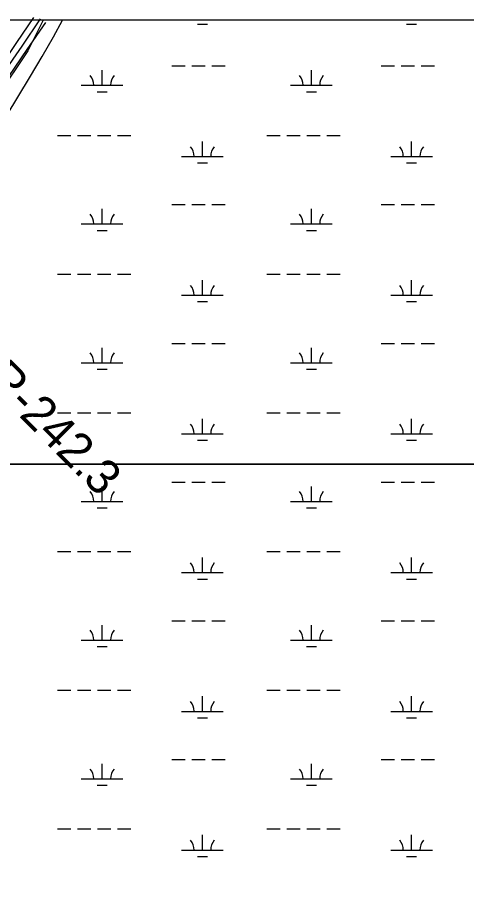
# Model space of a CAD drawing. Extents: x 3281947 to 3319794, y 715894 to 741249.
# Drawn here: x 3309600 to 3310677, y 737375 to 739476 of the extents above; entities that cross this region are included whole.
import ezdxf

# ---------------------------------------------------------------- set-up
doc = ezdxf.new("R2010")
doc.units = 0
for name, color, linetype in [('V-GRID-FRAM', 7, 'Continuous'), ('V-RIVR-RANG-IDEN', 7, 'Continuous'), ('V-ROAD-CNTR', 7, 'Continuous'), ('V-SITE-VEGE', 7, 'Continuous'), ('V-TOPO-MINR', 7, 'Continuous'), ('V-WETL-SWMP', 7, 'Continuous')]:
    doc.layers.add(name, color=color, linetype=linetype)

msp = doc.modelspace()

# ---------------------------------------------------------------- linework, layer by layer
at = {"layer": 'V-GRID-FRAM'}
msp.add_lwpolyline([(3286080.7, 739456.2), (3317564.6, 739474.5), (3317583.1, 721289.3), (3286083.3, 721271), (3286080.7, 739456.2)], dxfattribs=at)
at = {"layer": 'V-ROAD-CNTR'}
for points in [[(3309638.7, 739475.9), (3309597.9, 739416.1), (3309553.5, 739350.9), (3309551.3, 739347.7), (3309549.1, 739344.5), (3309547.1, 739341.4), (3309545.1, 739338.3), (3309541.4, 739332.5), (3309538, 739326.9), (3309534.8, 739321.7), (3309531.9, 739316.8), (3309529.2, 739312.2), (3309526.7, 739307.9), (3309524.3, 739303.8), (3309520, 739296.1), (3309516.3, 739289.4), (3309513.1, 739283.5), (3309507.6, 739273.2), (3309503.4, 739265.5), (3309491.2, 739242.3)], [(3309654.7, 739472.7), (3309610.3, 739407.6), (3309565.9, 739342.5), (3309563.7, 739339.3), (3309561.7, 739336.2), (3309559.7, 739333.2), (3309557.8, 739330.2), (3309554.1, 739324.5), (3309550.8, 739319.1), (3309547.7, 739314), (3309544.8, 739309.2), (3309542.1, 739304.7), (3309539.7, 739300.4), (3309537.4, 739296.4), (3309533.1, 739288.8), (3309529.5, 739282.2), (3309526.3, 739276.4), (3309520.8, 739266.2), (3309516.7, 739258.5), (3309504.5, 739235.3)], [(3309667.1, 739464.3), (3309622.7, 739399.2), (3309578.3, 739334.1), (3309576.2, 739331), (3309574.2, 739327.9), (3309572.2, 739325), (3309570.4, 739322.1), (3309566.8, 739316.5), (3309563.5, 739311.2), (3309560.5, 739306.3), (3309557.7, 739301.5), (3309555.1, 739297.1), (3309552.7, 739292.9), (3309550.4, 739289), (3309546.2, 739281.5), (3309542.6, 739275), (3309539.5, 739269.2), (3309534, 739259.1), (3309529.9, 739251.4), (3309517.8, 739228.4)]]:
    msp.add_lwpolyline(points, dxfattribs=at)
at = {"layer": 'V-SITE-VEGE'}
msp.add_line((3313381, 739472.1), (3309489.2, 739469.8), dxfattribs=at)
at = {"layer": 'V-TOPO-MINR'}
msp.add_lwpolyline([(3309520.4, 739144.1), (3309522, 739147.2), (3309534.3, 739170.3), (3309546.8, 739193.3), (3309559.8, 739216.1), (3309573.1, 739238.6), (3309631.4, 739335.3), (3309659.1, 739382.4), (3309686.2, 739429.8), (3309708, 739469.9)], dxfattribs=at)
at = {"layer": 'V-WETL-SWMP'}
for p, q in [((3309661.3, 739469.9), (3309624.5, 739396.3)), ((3313381, 739472.1), (3309661.3, 739469.9)), ((3310031.5, 739459.8), (3310055.5, 739459.8)), ((3310533.4, 739459.8), (3310557.4, 739459.8)), ((3309624.5, 739396.3), (3309546.4, 739279.2)), ((3309803, 739313.4), (3309803, 739349.4)), ((3309970.1, 739359.8), (3310002.1, 739359.8)), ((3310018.1, 739359.8), (3310050.1, 739359.8)), ((3310066.1, 739359.8), (3310098.1, 739359.8)), ((3310304.9, 739313.4), (3310304.9, 739349.4)), ((3310472, 739359.8), (3310504, 739359.8)), ((3310520, 739359.8), (3310552, 739359.8)), ((3310568, 739359.8), (3310600, 739359.8)), ((3309753, 739313.4), (3309853, 739313.4)), ((3310254.9, 739313.4), (3310354.9, 739313.4)), ((3309791, 739297.9), (3309815, 739297.9)), ((3310292.9, 739297.9), (3310316.9, 739297.9)), ((3309696.2, 739193.3), (3309728.2, 739193.3)), ((3309744.2, 739193.3), (3309776.2, 739193.3)), ((3309792.2, 739193.3), (3309824.2, 739193.3)), ((3309840.2, 739193.3), (3309872.2, 739193.3)), ((3310198.1, 739193.3), (3310230.1, 739193.3)), ((3310246.1, 739193.3), (3310278.1, 739193.3)), ((3310294.1, 739193.3), (3310326.1, 739193.3)), ((3310342.1, 739193.3), (3310374.1, 739193.3)), ((3310043.5, 739142.5), (3310043.5, 739178.5)), ((3310545.4, 739142.5), (3310545.4, 739178.5)), ((3309993.5, 739142.5), (3310093.5, 739142.5)), ((3310495.4, 739142.5), (3310595.4, 739142.5)), ((3310031.5, 739127.1), (3310055.5, 739127.1)), ((3310533.4, 739127.1), (3310557.4, 739127.1)), ((3309970.1, 739027.1), (3310002.1, 739027.1)), ((3310018.1, 739027.1), (3310050.1, 739027.1)), ((3310066.1, 739027.1), (3310098.1, 739027.1)), ((3310472, 739027.1), (3310504, 739027.1)), ((3310520, 739027.1), (3310552, 739027.1)), ((3310568, 739027.1), (3310600, 739027.1)), ((3309803, 738980.7), (3309803, 739016.7)), ((3310304.9, 738980.7), (3310304.9, 739016.7)), ((3309753, 738980.7), (3309853, 738980.7)), ((3309791, 738965.3), (3309815, 738965.3)), ((3310254.9, 738980.7), (3310354.9, 738980.7)), ((3310292.9, 738965.3), (3310316.9, 738965.3)), ((3309696.2, 738860.6), (3309728.2, 738860.6)), ((3309744.2, 738860.6), (3309776.2, 738860.6)), ((3309792.2, 738860.6), (3309824.2, 738860.6)), ((3309840.2, 738860.6), (3309872.2, 738860.6)), ((3310198.1, 738860.6), (3310230.1, 738860.6)), ((3310246.1, 738860.6), (3310278.1, 738860.6)), ((3310294.1, 738860.6), (3310326.1, 738860.6)), ((3310342.1, 738860.6), (3310374.1, 738860.6)), ((3310043.5, 738809.9), (3310043.5, 738845.9)), ((3310545.4, 738809.9), (3310545.4, 738845.9)), ((3309993.5, 738809.9), (3310093.5, 738809.9)), ((3310031.5, 738794.4), (3310055.5, 738794.4)), ((3310495.4, 738809.9), (3310595.4, 738809.9)), ((3310533.4, 738794.4), (3310557.4, 738794.4)), ((3309970.1, 738694.4), (3310002.1, 738694.4)), ((3310018.1, 738694.4), (3310050.1, 738694.4)), ((3310066.1, 738694.4), (3310098.1, 738694.4)), ((3310472, 738694.4), (3310504, 738694.4)), ((3310520, 738694.4), (3310552, 738694.4)), ((3310568, 738694.4), (3310600, 738694.4)), ((3309803, 738648), (3309803, 738684)), ((3310304.9, 738648), (3310304.9, 738684)), ((3309753, 738648), (3309853, 738648)), ((3310254.9, 738648), (3310354.9, 738648)), ((3309791, 738632.6), (3309815, 738632.6)), ((3310292.9, 738632.6), (3310316.9, 738632.6)), ((3309696.2, 738527.9), (3309728.2, 738527.9)), ((3309744.2, 738527.9), (3309776.2, 738527.9)), ((3309792.2, 738527.9), (3309824.2, 738527.9)), ((3309840.2, 738527.9), (3309872.2, 738527.9)), ((3310198.1, 738527.9), (3310230.1, 738527.9)), ((3310246.1, 738527.9), (3310278.1, 738527.9)), ((3310294.1, 738527.9), (3310326.1, 738527.9)), ((3310342.1, 738527.9), (3310374.1, 738527.9)), ((3310043.5, 738477.2), (3310043.5, 738513.2)), ((3310545.4, 738477.2), (3310545.4, 738513.2)), ((3309993.5, 738477.2), (3310093.5, 738477.2)), ((3310031.5, 738461.8), (3310055.5, 738461.8)), ((3310495.4, 738477.2), (3310595.4, 738477.2)), ((3310533.4, 738461.8), (3310557.4, 738461.8)), ((3308633.8, 738404.7), (3314234, 738404.7)), ((3309970.1, 738361.8), (3310002.1, 738361.8)), ((3310018.1, 738361.8), (3310050.1, 738361.8)), ((3310066.1, 738361.8), (3310098.1, 738361.8)), ((3310472, 738361.8), (3310504, 738361.8)), ((3310520, 738361.8), (3310552, 738361.8)), ((3310568, 738361.8), (3310600, 738361.8)), ((3309803, 738315.3), (3309803, 738351.3)), ((3310304.9, 738315.3), (3310304.9, 738351.3)), ((3309753, 738315.3), (3309853, 738315.3)), ((3310254.9, 738315.3), (3310354.9, 738315.3)), ((3309791, 738299.9), (3309815, 738299.9)), ((3310292.9, 738299.9), (3310316.9, 738299.9)), ((3309696.2, 738195.3), (3309728.2, 738195.3)), ((3309744.2, 738195.3), (3309776.2, 738195.3)), ((3309792.2, 738195.3), (3309824.2, 738195.3)), ((3309840.2, 738195.3), (3309872.2, 738195.3)), ((3310198.1, 738195.3), (3310230.1, 738195.3)), ((3310246.1, 738195.3), (3310278.1, 738195.3)), ((3310294.1, 738195.3), (3310326.1, 738195.3)), ((3310342.1, 738195.3), (3310374.1, 738195.3)), ((3310043.5, 738144.5), (3310043.5, 738180.5)), ((3310545.4, 738144.5), (3310545.4, 738180.5)), ((3309993.5, 738144.5), (3310093.5, 738144.5)), ((3310495.4, 738144.5), (3310595.4, 738144.5)), ((3310031.5, 738129.1), (3310055.5, 738129.1)), ((3310533.4, 738129.1), (3310557.4, 738129.1)), ((3309803, 737982.7), (3309803, 738018.7)), ((3309970.1, 738029.1), (3310002.1, 738029.1)), ((3310018.1, 738029.1), (3310050.1, 738029.1)), ((3310066.1, 738029.1), (3310098.1, 738029.1)), ((3310304.9, 737982.7), (3310304.9, 738018.7)), ((3310472, 738029.1), (3310504, 738029.1)), ((3310520, 738029.1), (3310552, 738029.1)), ((3310568, 738029.1), (3310600, 738029.1)), ((3309753, 737982.7), (3309853, 737982.7)), ((3310254.9, 737982.7), (3310354.9, 737982.7)), ((3309791, 737967.2), (3309815, 737967.2)), ((3310292.9, 737967.2), (3310316.9, 737967.2)), ((3309696.2, 737862.6), (3309728.2, 737862.6)), ((3309744.2, 737862.6), (3309776.2, 737862.6)), ((3309792.2, 737862.6), (3309824.2, 737862.6)), ((3309840.2, 737862.6), (3309872.2, 737862.6)), ((3310198.1, 737862.6), (3310230.1, 737862.6)), ((3310246.1, 737862.6), (3310278.1, 737862.6)), ((3310294.1, 737862.6), (3310326.1, 737862.6)), ((3310342.1, 737862.6), (3310374.1, 737862.6)), ((3310043.5, 737811.8), (3310043.5, 737847.8)), ((3310545.4, 737811.8), (3310545.4, 737847.8)), ((3309993.5, 737811.8), (3310093.5, 737811.8)), ((3310495.4, 737811.8), (3310595.4, 737811.8)), ((3310031.5, 737796.4), (3310055.5, 737796.4)), ((3310533.4, 737796.4), (3310557.4, 737796.4)), ((3309803, 737650), (3309803, 737686)), ((3309970.1, 737696.4), (3310002.1, 737696.4)), ((3310018.1, 737696.4), (3310050.1, 737696.4)), ((3310066.1, 737696.4), (3310098.1, 737696.4)), ((3310304.9, 737650), (3310304.9, 737686)), ((3310472, 737696.4), (3310504, 737696.4)), ((3310520, 737696.4), (3310552, 737696.4)), ((3310568, 737696.4), (3310600, 737696.4)), ((3309753, 737650), (3309853, 737650)), ((3310254.9, 737650), (3310354.9, 737650)), ((3309791, 737634.5), (3309815, 737634.5)), ((3310292.9, 737634.5), (3310316.9, 737634.5)), ((3309696.2, 737529.9), (3309728.2, 737529.9)), ((3309744.2, 737529.9), (3309776.2, 737529.9)), ((3309792.2, 737529.9), (3309824.2, 737529.9)), ((3309840.2, 737529.9), (3309872.2, 737529.9)), ((3310043.5, 737479.2), (3310043.5, 737515.2)), ((3310198.1, 737529.9), (3310230.1, 737529.9)), ((3310246.1, 737529.9), (3310278.1, 737529.9)), ((3310294.1, 737529.9), (3310326.1, 737529.9)), ((3310342.1, 737529.9), (3310374.1, 737529.9)), ((3310545.4, 737479.2), (3310545.4, 737515.2)), ((3309993.5, 737479.2), (3310093.5, 737479.2)), ((3310495.4, 737479.2), (3310595.4, 737479.2)), ((3310031.5, 737463.7), (3310055.5, 737463.7)), ((3310533.4, 737463.7), (3310557.4, 737463.7))]:
    msp.add_line(p, q, dxfattribs=at)
msp.add_lwpolyline([(3314234, 738404.7), (3308633.8, 738404.7)], dxfattribs=at)
for centre, start, end in [((3309747.8, 739313.8), 359.2282, 40.7718), ((3309858.2, 739313.8), 139.2282, 180.7718), ((3310249.7, 739313.8), 359.2282, 40.7718), ((3310360.2, 739313.8), 139.2282, 180.7718), ((3309988.2, 739143), 359.2282, 40.7718), ((3310098.7, 739143), 139.2282, 180.7718), ((3310490.1, 739143), 359.2282, 40.7718), ((3310600.6, 739143), 139.2282, 180.7718), ((3309747.8, 738981.2), 359.2282, 40.7718), ((3309858.2, 738981.2), 139.2282, 180.7718), ((3310249.7, 738981.2), 359.2282, 40.7718), ((3310360.2, 738981.2), 139.2282, 180.7718), ((3309988.2, 738810.3), 359.2282, 40.7718), ((3310098.7, 738810.3), 139.2282, 180.7718), ((3310490.1, 738810.3), 359.2282, 40.7718), ((3310600.6, 738810.3), 139.2282, 180.7718), ((3309747.8, 738648.5), 359.2282, 40.7718), ((3309858.2, 738648.5), 139.2282, 180.7718), ((3310249.7, 738648.5), 359.2282, 40.7718), ((3310360.2, 738648.5), 139.2282, 180.7718), ((3309988.2, 738477.7), 359.2282, 40.7718), ((3310098.7, 738477.7), 139.2282, 180.7718), ((3310490.1, 738477.7), 359.2282, 40.7718), ((3310600.6, 738477.7), 139.2282, 180.7718), ((3309747.8, 738315.8), 359.2282, 40.7718), ((3309858.3, 738315.8), 139.2282, 180.7718), ((3310249.7, 738315.8), 359.2282, 40.7718), ((3310360.2, 738315.8), 139.2282, 180.7718), ((3309988.2, 738145), 359.2282, 40.7718), ((3310098.7, 738145), 139.2282, 180.7718), ((3310490.1, 738145), 359.2282, 40.7718), ((3310600.6, 738145), 139.2282, 180.7718), ((3309747.8, 737983.1), 359.2282, 40.7718), ((3309858.3, 737983.1), 139.2282, 180.7718), ((3310249.7, 737983.1), 359.2282, 40.7718), ((3310360.2, 737983.1), 139.2282, 180.7718), ((3309988.2, 737812.3), 359.2282, 40.7718), ((3310098.7, 737812.3), 139.2282, 180.7718), ((3310490.1, 737812.3), 359.2282, 40.7718), ((3310600.6, 737812.3), 139.2282, 180.7718), ((3309747.8, 737650.5), 359.2282, 40.7718), ((3309858.3, 737650.5), 139.2282, 180.7718), ((3310249.7, 737650.5), 359.2282, 40.7718), ((3310360.2, 737650.5), 139.2282, 180.7718), ((3309988.2, 737479.6), 359.2282, 40.7718), ((3310098.7, 737479.6), 139.2282, 180.7718), ((3310490.1, 737479.6), 359.2282, 40.7718), ((3310600.6, 737479.6), 139.2282, 180.7718)]:
    msp.add_arc(centre, 35.2, start, end, dxfattribs=at)

# ---------------------------------------------------------------- texts
at = {"layer": 'V-RIVR-RANG-IDEN'}
msp.add_text('R-242.3', height=83, rotation=314.8926, dxfattribs=at).set_placement((3309519, 738603.8))

doc.saveas('drawing.dxf')
